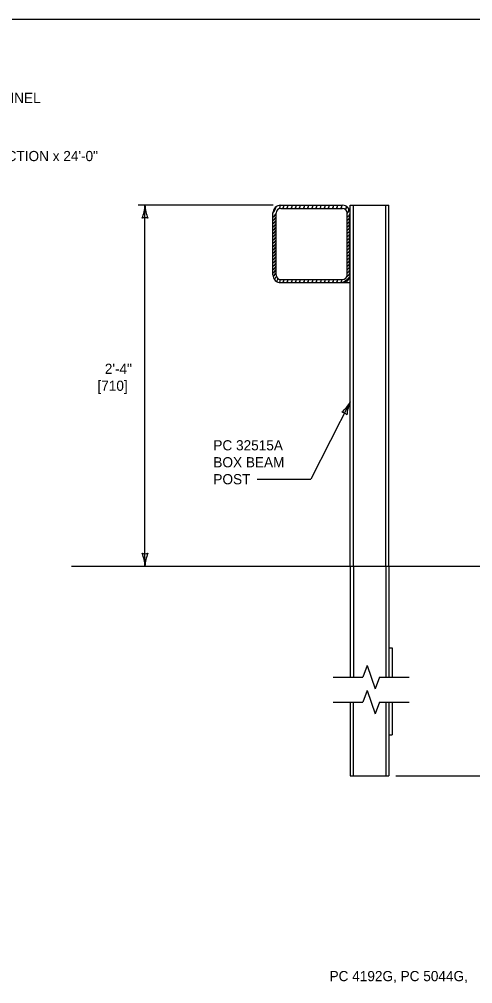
# Model space of a CAD drawing. Extents: x 49991.4 to 50021, y 49987.6 to 50011.4.
# Drawn here: x 50004.45 to 50007.12, y 49993.31 to 49999 of the extents above; entities that cross this region are included whole.
import ezdxf

# ---------------------------------------------------------------- set-up
doc = ezdxf.new("R2010")
doc.units = 0
for name, color, linetype in [('Level 1', 7, 'Continuous'), ('Level 2', 7, 'Continuous'), ('Level 3', 7, 'Continuous'), ('Level 4', 7, 'Continuous'), ('Level 6', 7, 'Continuous')]:
    doc.layers.add(name, color=color, linetype=linetype)

msp = doc.modelspace()

# ---------------------------------------------------------------- linework, layer by layer
at = {"layer": 'Level 1'}
for p, q in [((50005.9904, 49997.9021), (50006.3552, 49997.9021)), ((50006.4008, 49995.7737), (50006.4008, 49997.9021)), ((50006.4008, 49997.9021), (50006.6289, 49997.9021)), ((50006.4191, 49995.7737), (50006.4191, 49997.9021)), ((50006.6107, 49995.7737), (50006.6107, 49997.9021)), ((50006.6289, 49995.7737), (50006.6289, 49997.9021)), ((50005.9448, 49997.4915), (50005.9448, 49997.8565)), ((50005.9631, 49997.4917), (50005.9631, 49997.8565)), ((50005.9904, 49997.8839), (50006.3553, 49997.8839)), ((50006.3827, 49997.4917), (50006.3827, 49997.8565)), ((50005.9904, 49997.4643), (50006.3553, 49997.4643)), ((50005.9904, 49997.4459), (50006.4008, 49997.4459)), ((50004.756, 49995.7737), (50007.2567, 49995.7737))]:
    msp.add_line(p, q, dxfattribs=at)
msp.add_lwpolyline([(49999.3835, 49998.9992), (50016.7501, 49998.9992), (50016.7501, 49987.7988), (49999.3835, 49987.7988)], close=True, dxfattribs=at)
for points in [[(50005.9448, 49997.8565), (50005.9541, 49997.8691), (50005.9581, 49997.8777), (50005.9639, 49997.8937)], [(50005.9813, 49997.8823), (50005.9838, 49997.8855), (50005.9873, 49997.8922), (50005.9877, 49997.902)], [(50006.0026, 49997.8839), (50006.0085, 49997.8929), (50006.0083, 49997.9021)], [(50006.0271, 49997.8839), (50006.0329, 49997.8929), (50006.0327, 49997.9021)], [(50006.0515, 49997.8839), (50006.0573, 49997.8929), (50006.0571, 49997.9021)], [(50006.0759, 49997.8839), (50006.0817, 49997.8929), (50006.0815, 49997.9021)], [(50006.1003, 49997.8839), (50006.1062, 49997.8929), (50006.106, 49997.9021)], [(50006.1248, 49997.8839), (50006.1306, 49997.8929), (50006.1304, 49997.9021)], [(50006.1492, 49997.8839), (50006.155, 49997.8929), (50006.1548, 49997.9021)], [(50006.1736, 49997.8839), (50006.1794, 49997.8929), (50006.1792, 49997.9021)], [(50006.198, 49997.8839), (50006.2039, 49997.8929), (50006.2037, 49997.9021)], [(50006.2225, 49997.8839), (50006.2283, 49997.8929), (50006.2281, 49997.9021)], [(50006.2469, 49997.8839), (50006.2527, 49997.8929), (50006.2525, 49997.9021)], [(50006.2713, 49997.8839), (50006.2771, 49997.8929), (50006.2769, 49997.9021)], [(50006.2957, 49997.8839), (50006.3016, 49997.8929), (50006.3014, 49997.9021)], [(50006.3202, 49997.8839), (50006.326, 49997.8929), (50006.3258, 49997.9021)], [(50006.3446, 49997.8839), (50006.3504, 49997.8929), (50006.3502, 49997.9021)], [(50006.3721, 49997.8781), (50006.3781, 49997.8874), (50006.3779, 49997.896)], [(50005.9448, 49997.8328), (50005.9547, 49997.8392), (50005.9589, 49997.8477), (50005.9631, 49997.856)], [(50005.9448, 49997.8134), (50005.9547, 49997.8199), (50005.9589, 49997.8284), (50005.9631, 49997.8366)], [(50006.3827, 49997.853), (50006.3927, 49997.8685), (50006.3924, 49997.8828)], [(50006.3827, 49997.8336), (50006.3924, 49997.84), (50006.3966, 49997.8485), (50006.4008, 49997.8567)], [(50006.3827, 49997.8143), (50006.3924, 49997.8207), (50006.3966, 49997.8292), (50006.4008, 49997.8374)], [(50005.9448, 49997.7941), (50005.9547, 49997.8005), (50005.9589, 49997.809), (50005.9631, 49997.8173)], [(50005.9448, 49997.7747), (50005.9547, 49997.7812), (50005.9589, 49997.7897), (50005.9631, 49997.7979)], [(50005.9448, 49997.7554), (50005.9547, 49997.7619), (50005.9589, 49997.7704), (50005.9631, 49997.7786)], [(50006.3827, 49997.7949), (50006.3924, 49997.8013), (50006.3966, 49997.8098), (50006.4008, 49997.8181)], [(50006.3827, 49997.7756), (50006.3924, 49997.782), (50006.3966, 49997.7905), (50006.4008, 49997.7987)], [(50006.3827, 49997.7562), (50006.3924, 49997.7626), (50006.3966, 49997.7711), (50006.4008, 49997.7794)], [(50005.9448, 49997.736), (50005.9547, 49997.7425), (50005.9589, 49997.751), (50005.9631, 49997.7593)], [(50005.9448, 49997.7167), (50005.9547, 49997.7232), (50005.9589, 49997.7317), (50005.9631, 49997.7399)], [(50005.9448, 49997.6973), (50005.9547, 49997.7038), (50005.9589, 49997.7123), (50005.9631, 49997.7206)], [(50006.3827, 49997.7369), (50006.3924, 49997.7433), (50006.3966, 49997.7518), (50006.4008, 49997.76)], [(50006.3827, 49997.7175), (50006.3924, 49997.7239), (50006.3966, 49997.7324), (50006.4008, 49997.7407)], [(50006.3827, 49997.6982), (50006.3924, 49997.7046), (50006.3966, 49997.7131), (50006.4008, 49997.7213)], [(50005.9448, 49997.678), (50005.9547, 49997.6845), (50005.9589, 49997.693), (50005.9631, 49997.7012)], [(50005.9448, 49997.6586), (50005.9547, 49997.6651), (50005.9589, 49997.6736), (50005.9631, 49997.6819)], [(50005.9448, 49997.6393), (50005.9547, 49997.6458), (50005.9589, 49997.6543), (50005.9631, 49997.6625)], [(50006.3827, 49997.6788), (50006.3924, 49997.6852), (50006.3966, 49997.6937), (50006.4008, 49997.702)], [(50006.3827, 49997.6595), (50006.3924, 49997.6659), (50006.3966, 49997.6744), (50006.4008, 49997.6826)], [(50006.3827, 49997.6401), (50006.3924, 49997.6465), (50006.3966, 49997.655), (50006.4008, 49997.6633)], [(50005.9448, 49997.6199), (50005.9547, 49997.6264), (50005.9589, 49997.6349), (50005.9631, 49997.6432)], [(50005.9448, 49997.6006), (50005.9547, 49997.6071), (50005.9589, 49997.6156), (50005.9631, 49997.6238)], [(50005.9448, 49997.5812), (50005.9547, 49997.5877), (50005.9589, 49997.5962), (50005.9631, 49997.6045)], [(50006.3827, 49997.6208), (50006.3924, 49997.6272), (50006.3966, 49997.6357), (50006.4008, 49997.6439)], [(50006.3827, 49997.6014), (50006.3924, 49997.6078), (50006.3966, 49997.6163), (50006.4008, 49997.6246)], [(50006.3827, 49997.5821), (50006.3924, 49997.5885), (50006.3966, 49997.597), (50006.4008, 49997.6052)], [(50005.9448, 49997.5619), (50005.9547, 49997.5684), (50005.9589, 49997.5769), (50005.9631, 49997.5851)], [(50005.9448, 49997.5425), (50005.9547, 49997.549), (50005.9589, 49997.5575), (50005.9631, 49997.5658)], [(50005.9448, 49997.5232), (50005.9547, 49997.5297), (50005.9589, 49997.5382), (50005.9631, 49997.5464)], [(50006.3827, 49997.5627), (50006.3924, 49997.5691), (50006.3966, 49997.5776), (50006.4008, 49997.5859)], [(50006.3827, 49997.5434), (50006.3924, 49997.5498), (50006.3966, 49997.5583), (50006.4008, 49997.5665)], [(50006.3827, 49997.5241), (50006.3924, 49997.5304), (50006.3966, 49997.5389), (50006.4008, 49997.5472)], [(50005.9448, 49997.5038), (50005.9547, 49997.5103), (50005.9589, 49997.5188), (50005.9631, 49997.5271)], [(50005.9453, 49997.4848), (50005.9547, 49997.491), (50005.9589, 49997.4995), (50005.9631, 49997.5077)], [(50006.3818, 49997.4848), (50006.3924, 49997.4917), (50006.3966, 49997.5002), (50006.4008, 49997.5085)], [(50006.3827, 49997.5047), (50006.3924, 49997.5111), (50006.3966, 49997.5196), (50006.4008, 49997.5278)], [(50005.9523, 49997.4664), (50005.9581, 49997.4702), (50005.9623, 49997.4787), (50005.9645, 49997.483)], [(50005.9642, 49997.4542), (50005.9701, 49997.458), (50005.9743, 49997.4665), (50005.9754, 49997.4688)], [(50005.983, 49997.4465), (50005.9839, 49997.4477), (50005.9874, 49997.4544), (50005.9878, 49997.4644)], [(50006.0026, 49997.4459), (50006.0086, 49997.4551), (50006.0084, 49997.4643)], [(50006.027, 49997.4459), (50006.033, 49997.4551), (50006.0328, 49997.4643)], [(50006.0515, 49997.4459), (50006.0574, 49997.4551), (50006.0572, 49997.4643)], [(50006.0759, 49997.4459), (50006.0818, 49997.4551), (50006.0816, 49997.4643)], [(50006.1003, 49997.4459), (50006.1063, 49997.4551), (50006.1061, 49997.4643)], [(50006.1247, 49997.4459), (50006.1307, 49997.4551), (50006.1305, 49997.4643)], [(50006.1492, 49997.4459), (50006.1551, 49997.4551), (50006.1549, 49997.4643)], [(50006.1736, 49997.4459), (50006.1795, 49997.4551), (50006.1793, 49997.4643)], [(50006.198, 49997.4459), (50006.204, 49997.4551), (50006.2038, 49997.4643)], [(50006.2224, 49997.4459), (50006.2284, 49997.4551), (50006.2282, 49997.4643)], [(50006.2469, 49997.4459), (50006.2528, 49997.4551), (50006.2526, 49997.4643)], [(50006.2713, 49997.4459), (50006.2772, 49997.4551), (50006.277, 49997.4643)], [(50006.2957, 49997.4459), (50006.3017, 49997.4551), (50006.3015, 49997.4643)], [(50006.3201, 49997.4459), (50006.3261, 49997.4551), (50006.3259, 49997.4643)], [(50006.3446, 49997.4459), (50006.3505, 49997.4551), (50006.3503, 49997.4643)], [(50006.3578, 49997.4459), (50006.3781, 49997.4623), (50006.3853, 49997.467), (50006.4008, 49997.4836)]]:
    msp.add_lwpolyline(points, dxfattribs=at)
for centre, radius, start, end in [((50005.9904, 49997.8565), 0.0456, 90, 180), ((50006.3552, 49997.8565), 0.0456, 360, 90), ((50005.9904, 49997.8565), 0.0274, 90, 180), ((50006.3553, 49997.8565), 0.0274, 360, 90), ((50005.9904, 49997.4915), 0.0456, 180, 270), ((50005.9904, 49997.4917), 0.0274, 180, 270), ((50006.3552, 49997.4915), 0.0456, 270, 360), ((50006.3553, 49997.4917), 0.0274, 270, 360)]:
    msp.add_arc(centre, radius, start, end, dxfattribs=at)
at = {"layer": 'Level 3'}
msp.add_line((50005.1898, 49995.7737), (50005.1898, 49997.9021), dxfattribs=at)
for points in [[(50005.9467, 49997.9021), (50005.1498, 49997.9021)], [(50006.4008, 49996.7425), (50006.1678, 49996.2864)], [(50005.8525, 49996.2867), (50006.1678, 49996.2864)], [(50006.6689, 49994.5375), (50007.2567, 49994.5375)]]:
    msp.add_lwpolyline(points, dxfattribs=at)
for centre, radius, start, end in [((50004.9676, 49997.9113), 0.2223, 337.456, 357.6395), ((50005.4225, 49997.9136), 0.233, 182.8273, 202.0772), ((50005.1898, 49997.7739), 0.0548, 72.1388, 107.8612), ((50006.2071, 49996.8517), 0.2223, 310.3909, 330.5744), ((50006.6132, 49996.6468), 0.233, 155.7622, 175.012), ((50006.3424, 49996.6283), 0.0548, 45.0737, 80.7961), ((50005.1898, 49995.9019), 0.0548, 252.1388, 287.8612), ((50004.9571, 49995.7622), 0.233, 2.8273, 22.0772), ((50005.4119, 49995.7645), 0.2223, 157.456, 177.6395)]:
    msp.add_arc(centre, radius, start, end, dxfattribs=at)
at = {"layer": 'Level 4'}
for p, q in [((50006.4008, 49995.7737), (50006.4008, 49995.1198)), ((50006.4191, 49995.7737), (50006.4191, 49995.1198)), ((50006.6107, 49995.7737), (50006.6107, 49995.1198)), ((50006.6289, 49995.7737), (50006.6289, 49995.1198)), ((50006.6289, 49995.2924), (50006.648, 49995.2924)), ((50006.648, 49995.2924), (50006.648, 49995.1198)), ((50006.4008, 49994.972), (50006.4008, 49994.5375)), ((50006.419, 49994.972), (50006.419, 49994.5375)), ((50006.6107, 49994.972), (50006.6107, 49994.5375)), ((50006.6289, 49994.972), (50006.6289, 49994.5375)), ((50006.648, 49994.972), (50006.648, 49994.7782)), ((50006.6289, 49994.7782), (50006.648, 49994.7782)), ((50006.4008, 49994.5375), (50006.6289, 49994.5375))]:
    msp.add_line(p, q, dxfattribs=at)
at = {"layer": 'Level 6'}
for p, q in [((50006.5001, 49995.1884), (50006.4758, 49995.1198)), ((50006.5001, 49995.1884), (50006.5244, 49995.1198)), ((50006.3008, 49995.1198), (50006.4758, 49995.1198)), ((50006.5244, 49995.1198), (50006.5487, 49995.0512)), ((50006.573, 49995.1198), (50006.5487, 49995.0512)), ((50006.573, 49995.1198), (50006.748, 49995.1198)), ((50006.5001, 49995.0406), (50006.4758, 49994.972)), ((50006.5001, 49995.0406), (50006.5244, 49994.972)), ((50006.3008, 49994.972), (50006.4758, 49994.972)), ((50006.5244, 49994.972), (50006.5487, 49994.9034)), ((50006.573, 49994.972), (50006.5487, 49994.9034)), ((50006.573, 49994.972), (50006.748, 49994.972))]:
    msp.add_line(p, q, dxfattribs=at)

# ---------------------------------------------------------------- texts
at = {"layer": 'Level 2'}
for s, p in [('REFLECTIVE CHANNEL', (50003.6735, 49998.5057)), ('TELESCOPING SECTION x 24\'-0"', (50003.6735, 49998.1627)), ('2\'-4"', (50004.9528, 49996.9079)), ('[710]', (50004.9093, 49996.8079)), ('PC 32515A', (50005.5933, 49996.4567)), ('BOX BEAM ', (50005.5933, 49996.3567)), ('POST', (50005.5933, 49996.2567)), ('PC 4192G, PC 5044G,', (50006.2788, 49993.3261))]:
    msp.add_text(s, height=0.06, dxfattribs=at).set_placement(p)

doc.saveas('drawing.dxf')
